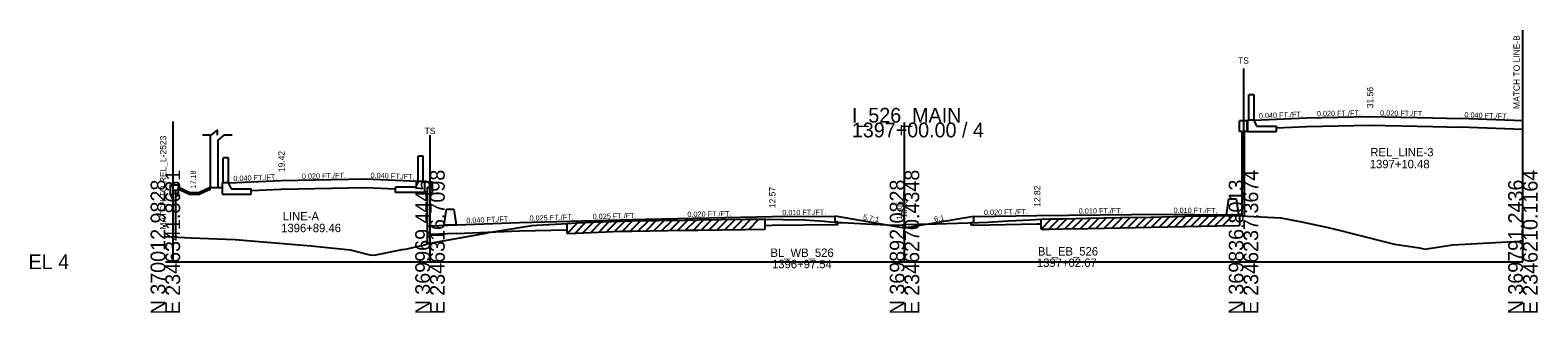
# Model space of a CAD drawing. Extents: x -170 to 2527928, y -10 to 1619750.
# Drawn here: x 1974.3 to 2260.8, y 7490.3 to 7544 of the extents above; entities that cross this region are included whole.
import ezdxf

# ---------------------------------------------------------------- set-up
doc = ezdxf.new("R2010")
doc.units = 0
for name, color, linetype in [('Default', 7, 'Continuous'), ('RD_GPK_XS_Cell', 7, 'Continuous'), ('RD_PD_NOISE-WALL-GM', 7, 'Continuous'), ('RD_PD_WallFill', 7, 'Continuous'), ('RD_XS_Base', 7, 'Continuous'), ('RD_XS_EarthShd', 7, 'Continuous'), ('RD_XS_ExGround', 7, 'Continuous'), ('RD_XS_ExPaveRet', 7, 'Continuous'), ('RD_XS_MatchLine', 7, 'Continuous'), ('RD_XS_Pave', 7, 'Continuous'), ('RD_XS_PaveShd', 7, 'Continuous'), ('RD_XS_TieSlope', 7, 'Continuous'), ('RD_XS_TX_Elev_EX', 7, 'Continuous'), ('RD_XS_TX_Elev_PR', 7, 'Continuous'), ('RD_XS_TX_Slope', 7, 'Continuous'), ('RD_XS_TX_Station', 7, 'Continuous')]:
    doc.layers.add(name, color=color, linetype=linetype)

msp = doc.modelspace()

# ---------------------------------------------------------------- linework, layer by layer
at = {"layer": 'Default'}
for p, q in [((2008.63, 7524.05), (2007.05, 7524.05)), ((2009.88, 7525.07), (2008.63, 7524.05)), ((2009.88, 7524.05), (2009.88, 7525.07)), ((2011.13, 7524.05), (2009.88, 7523.02)), ((2012.72, 7524.05), (2011.13, 7524.05))]:
    msp.add_line(p, q, dxfattribs=at)
at = {"layer": 'RD_GPK_XS_Cell'}
for p, q in [((2140.43, 7500), (2140.43, 7526.43)), ((2000, 7500), (2050.28, 7500)), ((2050.28, 7500), (2140.43, 7500)), ((2140.43, 7500), (2204.84, 7500)), ((2204.84, 7500), (2257.93, 7500))]:
    msp.add_line(p, q, dxfattribs=at)
at = {"layer": 'RD_PD_NOISE-WALL-GM'}
for p, q in [((2008.5, 7524.05), (2008.5, 7514.1)), ((2010, 7514.1), (2010, 7523.12)), ((2201.59, 7508.94), (2202.08, 7511.94)), ((2202.08, 7511.94), (2203.42, 7511.94)), ((2203.42, 7511.94), (2203.9, 7508.94)), ((2052.96, 7507.01), (2053.44, 7510.01)), ((2053.44, 7510.01), (2054.78, 7510.01)), ((2054.78, 7510.01), (2055.26, 7507.01)), ((2052.96, 7507.01), (2055.26, 7507.01))]:
    msp.add_line(p, q, dxfattribs=at)
at = {"layer": 'RD_PD_WallFill'}
for p, q in [((2205.84, 7526.92), (2205.84, 7531.68)), ((2206.84, 7531.68), (2205.84, 7531.68)), ((2206.84, 7526.92), (2206.84, 7531.68)), ((2204.06, 7524.76), (2204.06, 7526.76)), ((2205.56, 7526.76), (2204.06, 7526.76)), ((2205.72, 7526.92), (2205.55, 7526.76)), ((2205.56, 7524.76), (2205.56, 7526.76)), ((2205.63, 7526.76), (2205.56, 7526.76)), ((2205.63, 7526.84), (2205.63, 7524.76)), ((2206.84, 7526.92), (2205.72, 7526.92)), ((2206.84, 7526.92), (2206.84, 7526.76)), ((2206.84, 7526.76), (2207.34, 7525.76)), ((2207.34, 7525.76), (2211.13, 7525.76)), ((2211.13, 7524.76), (2211.13, 7525.76)), ((2257.93, 7504.1), (2257.93, 7526.74)), ((2204.56, 7524.76), (2204.06, 7524.76)), ((2204.56, 7508.77), (2204.56, 7524.76)), ((2205.06, 7508.73), (2205.06, 7524.76)), ((2205.56, 7524.76), (2205.06, 7524.76)), ((2205.56, 7524.76), (2211.13, 7524.76)), ((2205.63, 7524.76), (2205.56, 7524.76)), ((2011.08, 7519.77), (2011, 7519.69)), ((2011, 7515.02), (2011, 7519.69)), ((2011.92, 7519.77), (2011.08, 7519.77)), ((2011.92, 7519.77), (2012, 7519.69)), ((2012, 7515.02), (2012, 7519.69)), ((2048.08, 7520.09), (2048, 7520.01)), ((2048, 7515.34), (2048, 7520.01)), ((2048.08, 7520.09), (2048.92, 7520.09)), ((2048.92, 7520.09), (2049, 7520.01)), ((2049, 7515.34), (2049, 7520.01)), ((2001, 7514.6), (2002.5, 7514.6)), ((2001, 7512.6), (2001, 7514.6)), ((2002.5, 7512.6), (2002.5, 7514.6)), ((2004.5, 7513.18), (2002.5, 7514.1)), ((2008.5, 7514.1), (2006.5, 7513.18)), ((2008.5, 7513.73), (2008.5, 7514.1)), ((2010.87, 7515.02), (2010.79, 7514.93)), ((2010.79, 7514.93), (2010.79, 7512.85)), ((2012, 7515.02), (2010.87, 7515.02)), ((2012, 7515.02), (2012, 7514.85)), ((2012, 7514.85), (2012.49, 7513.85)), ((2047.51, 7514.17), (2043.71, 7514.17)), ((2043.71, 7513.17), (2043.71, 7514.17)), ((2048, 7515.17), (2047.51, 7514.17)), ((2048, 7515.34), (2049.13, 7515.34)), ((2048, 7515.34), (2048, 7515.17)), ((2049.13, 7515.34), (2049.29, 7515.17)), ((2049.21, 7515.25), (2049.21, 7513.17)), ((2049.21, 7515.17), (2049.28, 7515.17)), ((2049.28, 7513.17), (2049.28, 7515.17)), ((2049.28, 7515.17), (2050.78, 7515.17)), ((2049.78, 7514.17), (2050.28, 7514.17)), ((2049.78, 7503.44), (2049.78, 7514.17)), ((2050.28, 7503.56), (2050.28, 7514.17)), ((2050.78, 7513.17), (2050.78, 7515.17)), ((2001, 7512.6), (2001.5, 7512.6)), ((2001.5, 7504.72), (2001.5, 7513.6)), ((2001.5, 7513.6), (2002, 7513.6)), ((2002, 7504.7), (2002, 7513.6)), ((2002, 7512.6), (2002.5, 7512.6)), ((2004.43, 7512.85), (2002.5, 7513.73)), ((2004.43, 7512.85), (2006.57, 7512.85)), ((2004.5, 7513.18), (2006.5, 7513.18)), ((2008.5, 7513.73), (2006.57, 7512.85)), ((2010.79, 7512.85), (2016.29, 7512.85)), ((2012.49, 7513.85), (2016.29, 7513.85)), ((2016.29, 7512.85), (2016.29, 7513.85)), ((2049.28, 7513.17), (2043.71, 7513.17)), ((2049.21, 7513.17), (2049.28, 7513.17)), ((2049.28, 7513.17), (2049.78, 7513.17)), ((2050.28, 7513.17), (2050.78, 7513.17)), ((2201.59, 7508.94), (2204.56, 7508.94))]:
    msp.add_line(p, q, dxfattribs=at)
at = {"layer": 'RD_XS_Base'}
for p, q in [((2211.13, 7525.46), (2216.84, 7525.69)), ((2216.84, 7525.69), (2228.84, 7525.93)), ((2228.84, 7525.93), (2240.84, 7525.69)), ((2240.84, 7525.69), (2245.98, 7525.58)), ((2257.93, 7525.11), (2245.98, 7525.58)), ((2022, 7513.78), (2038, 7514.1)), ((2038, 7514.1), (2043.71, 7513.87)), ((2016.29, 7513.55), (2022, 7513.78)), ((2127.26, 7507.55), (2127.26, 7508.69)), ((2153.59, 7507.45), (2153.59, 7508.58)), ((2201.59, 7508.77), (2201.59, 7508.94)), ((2050.28, 7505.17), (2050.28, 7506.81)), ((2055.26, 7505.37), (2050.28, 7505.17)), ((2055.26, 7505.37), (2067.26, 7505.85)), ((2067.26, 7505.85), (2076.33, 7506.08)), ((2113.93, 7506.91), (2115.26, 7506.93)), ((2115.26, 7506.93), (2127.26, 7507.05)), ((2127.76, 7507.56), (2127.26, 7507.55)), ((2127.26, 7507.05), (2127.76, 7507.06)), ((2127.76, 7507.06), (2127.76, 7507.56)), ((2153.09, 7507.44), (2153.59, 7507.45)), ((2153.09, 7506.94), (2153.09, 7507.44)), ((2153.59, 7506.95), (2153.09, 7506.94)), ((2153.59, 7506.95), (2165.59, 7507.19)), ((2165.59, 7507.19), (2166.38, 7507.19))]:
    msp.add_line(p, q, dxfattribs=at)
at = {"layer": 'RD_XS_EarthShd'}
msp.add_line((2008.5, 7514.1), (2010.79, 7514.1), dxfattribs=at)
at = {"layer": 'RD_XS_ExGround'}
msp.add_lwpolyline([(2000, 7504.78), (2004.86, 7504.58), (2013.27, 7504.26), (2027.68, 7503.06), (2035.1, 7502.3), (2038.87, 7501.34), (2039.65, 7501.23), (2044.99, 7502.33), (2045.53, 7502.39), (2045.93, 7502.49), (2047.27, 7502.78), (2048.45, 7503.06), (2049.21, 7503.21), (2049.92, 7503.49), (2050.28, 7503.56), (2060.89, 7505.45), (2061.08, 7505.49), (2061.41, 7505.54), (2066.52, 7506.38), (2067.66, 7506.55), (2069.62, 7506.86), (2070.53, 7506.93), (2074.07, 7507.15), (2076.33, 7507.3), (2078.05, 7507.37), (2086.49, 7507.72), (2088.64, 7507.75), (2098.74, 7507.9), (2101.17, 7507.94), (2110.13, 7508.07), (2113.93, 7508.08), (2113.97, 7508.08), (2113.98, 7508.08), (2114, 7508.08), (2117.41, 7508.01), (2121.51, 7507.95), (2125.16, 7507.7), (2127.6, 7507.49), (2128.61, 7507.44), (2133.17, 7507.23), (2138.4, 7506.96), (2140.04, 7507.04), (2140.43, 7507.05), (2146.5, 7507.2), (2154.5, 7507.49), (2156.2, 7507.55), (2160.17, 7507.75), (2164.33, 7507.98), (2166.38, 7508.11), (2168.07, 7508.14), (2170.5, 7508.17), (2175.29, 7508.26), (2181.47, 7508.38), (2187.25, 7508.5), (2193.67, 7508.64), (2199.81, 7508.74), (2204.08, 7508.81), (2204.84, 7508.75), (2205.63, 7508.69), (2211.94, 7508.37), (2215.89, 7507.56), (2220.92, 7506.5), (2223, 7505.99), (2225.75, 7505.3), (2233.52, 7503.36), (2238.26, 7502.62), (2239.33, 7502.38), (2240.04, 7502.52), (2244.62, 7503.24), (2257.32, 7503.93), (2257.93, 7504.1)], dxfattribs=at)
at = {"layer": 'RD_XS_ExPaveRet'}
for p, q in [((2169.38, 7506.24), (2171.33, 7508.19)), ((2170.88, 7506.26), (2172.84, 7508.22)), ((2172.38, 7506.29), (2174.34, 7508.24)), ((2173.88, 7506.32), (2175.84, 7508.27)), ((2175.38, 7506.35), (2177.34, 7508.3)), ((2176.88, 7506.37), (2178.84, 7508.33)), ((2178.38, 7506.4), (2180.34, 7508.35)), ((2179.88, 7506.43), (2181.84, 7508.38)), ((2181.38, 7506.46), (2183.34, 7508.42)), ((2182.88, 7506.49), (2184.84, 7508.45)), ((2184.38, 7506.52), (2186.34, 7508.48)), ((2185.88, 7506.55), (2187.84, 7508.51)), ((2187.38, 7506.58), (2189.35, 7508.55)), ((2188.88, 7506.62), (2190.85, 7508.58)), ((2190.38, 7506.65), (2192.35, 7508.61)), ((2191.88, 7506.69), (2193.84, 7508.64)), ((2193.38, 7506.72), (2195.33, 7508.67)), ((2194.88, 7506.74), (2196.83, 7508.69)), ((2196.38, 7506.77), (2198.33, 7508.71)), ((2197.88, 7506.79), (2199.83, 7508.74)), ((2199.38, 7506.81), (2201.33, 7508.76)), ((2200.88, 7506.84), (2202.84, 7508.79)), ((2204.08, 7508.81), (2204.08, 7506.89)), ((2076.33, 7505.38), (2078.33, 7507.38)), ((2076.33, 7505.38), (2076.33, 7507.3)), ((2076.33, 7505.38), (2078.05, 7505.45)), ((2077.83, 7505.44), (2079.83, 7507.44)), ((2078.05, 7505.45), (2086.49, 7505.8)), ((2079.33, 7505.5), (2081.33, 7507.5)), ((2080.83, 7505.56), (2082.83, 7507.56)), ((2082.33, 7505.63), (2084.33, 7507.63)), ((2083.83, 7505.69), (2085.83, 7507.69)), ((2085.33, 7505.75), (2087.31, 7507.73)), ((2086.49, 7505.8), (2088.64, 7505.83)), ((2086.83, 7505.8), (2088.78, 7507.75)), ((2088.33, 7505.83), (2090.28, 7507.78)), ((2088.64, 7505.83), (2098.74, 7505.99)), ((2089.83, 7505.85), (2091.78, 7507.8)), ((2091.33, 7505.87), (2093.28, 7507.82)), ((2092.83, 7505.9), (2094.78, 7507.84)), ((2094.33, 7505.92), (2096.28, 7507.87)), ((2095.83, 7505.94), (2097.78, 7507.89)), ((2097.33, 7505.97), (2099.27, 7507.91)), ((2098.74, 7505.99), (2101.17, 7506.02)), ((2098.83, 7505.99), (2100.77, 7507.93)), ((2100.33, 7506.01), (2102.27, 7507.95)), ((2101.17, 7506.02), (2110.13, 7506.16)), ((2101.83, 7506.03), (2103.78, 7507.98)), ((2103.33, 7506.05), (2105.28, 7508)), ((2104.83, 7506.08), (2106.78, 7508.02)), ((2106.33, 7506.1), (2108.28, 7508.05)), ((2107.83, 7506.12), (2109.78, 7508.07)), ((2109.33, 7506.14), (2111.26, 7508.08)), ((2110.13, 7506.16), (2113.93, 7506.17)), ((2110.83, 7506.16), (2112.75, 7508.08)), ((2113.93, 7506.17), (2113.93, 7508.08)), ((2166.38, 7506.19), (2168.33, 7508.14)), ((2166.38, 7506.19), (2166.38, 7508.11)), ((2166.38, 7506.19), (2168.07, 7506.22)), ((2167.88, 7506.22), (2169.83, 7508.16)), ((2168.07, 7506.22), (2170.5, 7506.25)), ((2170.5, 7506.25), (2175.29, 7506.35)), ((2175.29, 7506.35), (2181.47, 7506.46)), ((2181.47, 7506.46), (2187.25, 7506.58)), ((2187.25, 7506.58), (2193.67, 7506.72)), ((2193.67, 7506.72), (2199.81, 7506.82)), ((2199.81, 7506.82), (2204.08, 7506.89))]:
    msp.add_line(p, q, dxfattribs=at)
at = {"layer": 'RD_XS_MatchLine'}
for p, q in [((2257.93, 7500), (2257.93, 7543.98)), ((2204.84, 7536.72), (2204.84, 7513.78)), ((2001.5, 7500), (2001.5, 7526.65)), ((2050.28, 7500), (2050.28, 7524.05))]:
    msp.add_line(p, q, dxfattribs=at)
at = {"layer": 'RD_XS_Pave'}
for p, q in [((2216.84, 7527.32), (2228.84, 7527.56)), ((2228.84, 7527.56), (2240.84, 7527.32)), ((2240.84, 7527.32), (2245.98, 7527.22)), ((2022, 7515.42), (2038, 7515.74)), ((2091.26, 7508.09), (2115.26, 7508.57)), ((2165.59, 7508.82), (2189.59, 7509.06)), ((2067.26, 7507.49), (2079.26, 7507.79)), ((2079.26, 7507.79), (2091.26, 7508.09))]:
    msp.add_line(p, q, dxfattribs=at)
at = {"layer": 'RD_XS_PaveShd'}
for p, q in [((2206.84, 7526.92), (2216.84, 7527.32)), ((2257.93, 7526.74), (2245.98, 7527.22)), ((2012, 7515.02), (2022, 7515.42)), ((2038, 7515.74), (2048, 7515.34)), ((2115.26, 7508.57), (2127.26, 7508.69)), ((2153.59, 7508.58), (2165.59, 7508.82)), ((2189.59, 7509.06), (2201.59, 7508.94)), ((2050.28, 7506.81), (2067.26, 7507.49))]:
    msp.add_line(p, q, dxfattribs=at)
at = {"layer": 'RD_XS_TieSlope'}
for p, q in [((2140.43, 7506.39), (2127.26, 7508.69)), ((2153.59, 7508.58), (2140.43, 7506.39))]:
    msp.add_line(p, q, dxfattribs=at)

# ---------------------------------------------------------------- texts
at = {"layer": 'RD_GPK_XS_Cell'}
for s, p in [('I_526_MAIN', (2130.43, 7526.43)), ('1397+00.00 / 4', (2130.43, 7523.63)), ('EL 4', (1974, 7498.6))]:
    msp.add_text(s, height=2.8, dxfattribs=at).set_placement(p)
for s, p in [('E 2346341.8631', (2002.8, 7490)), ('E 2346316.7098', (2053.08, 7490)), ('E 2346270.4348', (2143.23, 7490)), ('E 2346237.3674', (2207.64, 7490)), ('E 2346210.1164', (2260.73, 7490)), ('N 370012.9828', (2000, 7490)), ('N 369969.4445', (2050.28, 7490)), ('N 369892.0828', (2140.43, 7490)), ('N 369836.8013', (2204.84, 7490)), ('N 369791.2436', (2257.93, 7490))]:
    msp.add_text(s, height=2.8, rotation=90, dxfattribs=at).set_placement(p)
at = {"layer": 'RD_XS_MatchLine'}
for s, p in [('MATCH TO LINE-B', (2257.34, 7529.03)), ('MATCH TO REL_L-2523', (2000.17, 7506.11))]:
    msp.add_text(s, height=1.2, rotation=90, dxfattribs=at).set_placement(p)
for p in [(2203.82, 7537.6), (2049.26, 7524.25)]:
    msp.add_text('TS', height=1.2, dxfattribs=at).set_placement(p)
at = {"layer": 'RD_XS_TX_Elev_EX'}
msp.add_text('11.05', height=1, rotation=90, dxfattribs=at).set_placement((2139.93, 7508.05))
at = {"layer": 'RD_XS_TX_Elev_PR'}
msp.add_text('10.39', height=1, rotation=90, dxfattribs=at).set_placement((2140.93, 7508.39))
at = {"layer": 'RD_XS_TX_Slope'}
for s, rotation, p in [('0.040 FT./FT.', 2.2906, (2207.78, 7527.21)), ('0.020 FT./FT.', 1.1458, (2218.79, 7527.61)), ('0.020 FT./FT.', 358.8542, (2230.8, 7527.77)), ('0.040 FT./FT.', 357.7094, (2246.81, 7527.44)), ('17.18', 90, (2005.79, 7513.89)), ('0.020 FT./FT.', 1.1458, (2025.94, 7515.74)), ('0.040 FT./FT.', 357.7094, (2038.96, 7515.95)), ('0.040 FT./FT.', 2.2906, (2012.94, 7515.3)), ('0.040 FT./FT.', 2.2906, (2057.2, 7507.34)), ('0.025 FT./FT.', 1.4321, (2069.2, 7507.79)), ('0.025 FT./FT.', 1.4321, (2081.2, 7508.09)), ('0.020 FT./FT.', 1.1458, (2099.2, 7508.5)), ('0.010 FT./FT.', 0.5702, (2117.21, 7508.84)), ('5.7:1', 350.088, (2132.5, 7508.03)), ('6:1', 9.4623, (2146.14, 7507.59)), ('0.020 FT./FT.', 1.1458, (2155.54, 7508.87)), ('0.010 FT./FT.', 0.5716, (2173.54, 7509.15)), ('0.010 FT./FT.', 359.4231, (2191.54, 7509.29))]:
    msp.add_text(s, height=1, rotation=rotation, dxfattribs=at).set_placement(p)
at = {"layer": 'RD_XS_TX_Station'}
for s, p in [(' 31.56', (2229.5, 7528.73)), (' 19.42', (2022.66, 7516.59)), (' 12.57', (2115.92, 7509.74)), (' 12.82', (2166.25, 7509.99))]:
    msp.add_text(s, height=1.2, rotation=90, dxfattribs=at).set_placement(p)
for s, p in [('REL_LINE-3', (2228.94, 7520.02)), ('1397+10.48', (2228.84, 7517.76)), ('LINE-A', (2022.29, 7507.87)), ('1396+89.46', (2022, 7505.62)), ('BL_WB_526', (2114.97, 7500.92)), ('BL_EB_526', (2165.79, 7501.18)), ('1396+97.54', (2115.26, 7498.77)), ('1397+02.67', (2165.59, 7499.02))]:
    msp.add_text(s, height=1.6, dxfattribs=at).set_placement(p)

doc.saveas('drawing.dxf')
